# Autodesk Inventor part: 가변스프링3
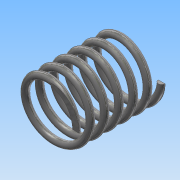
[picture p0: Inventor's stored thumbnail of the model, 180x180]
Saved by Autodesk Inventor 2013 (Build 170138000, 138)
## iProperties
Created: 2019-07
Part Number: 가변스프링3
Material: 강철, 탄소
Document SubType Name: Modeling
Designer: Administrator
Density: 7.87 g/cm^3
Mass: 7.79515 g
Surface Area: 20.0756 cm^2
Volume: 0.990489 cm^3
Author: Administrator
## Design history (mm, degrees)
sketch "스케치1"
  geometry: L1 (0, 0)-(0, 25.33); L2 (0, 25.33)-(16.881, 25.33); C1 r 1 at (8.5, 0)
  constraints: 4 end point, 1 centre point, 1 horizontal alignment, 1 perpendicular, 1 vertical
  dimensions: "d0" = 25.33013 distance of L1.start L1.end (derived); "d1" = 2 diameter of C1; "d2" = 17 diameter of C1.centre L1
feature "코일1" sketch "스케치1" pitch "d3" = 10; turns "d5" = 6; dims "d4" = 25.33013 (= d0), "d6" = 0, angle "d7" = 90 deg, angle "d8" = 90 deg, "d9" = 0, "d10" = 0
sketch "스케치2"
  geometry: L1 (0, 12.5)-(25.33, 12.5); L2 (25.33, 12.5)-(25.33, -12.5); L3 (25.33, -12.5)-(0, -12.5); L4 (0, -12.5)-(0, 12.5); 2 further points
  constraints: 8 end point, 2 parallel, 1 coincident, 1 horizontal, 1 midpoint, 1 perpendicular
  dimensions: "d11" = 25.33013 distance between parallel lines of L2 L4 (derived); "d13" = 25 distance between parallel lines of L1 L3
extrude "돌출1" sketch "스케치2" stored distance "d14" = 50; taper "d15" = 0 deg
node "솔리드1"
